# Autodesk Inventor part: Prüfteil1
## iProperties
Created: 2008-11
Part Number: Prüfteil1
Project: Anlage
Material: Aluminium
Description: Leiste
Document SubType Name: Modellieren
Designer: GEIKON
Manufacturer: Standard
Standards Organization: Custom
Mass: 2179.97 g
Surface Area: 3056.97 cm^2
Volume: 804.417 cm^3
Density: 2.71 g/cm^3
Author: GEIKON
Revision Number: 00
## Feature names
1. Extrusion5
2. Extrusion7
3. Bohrung5 [Hole]
